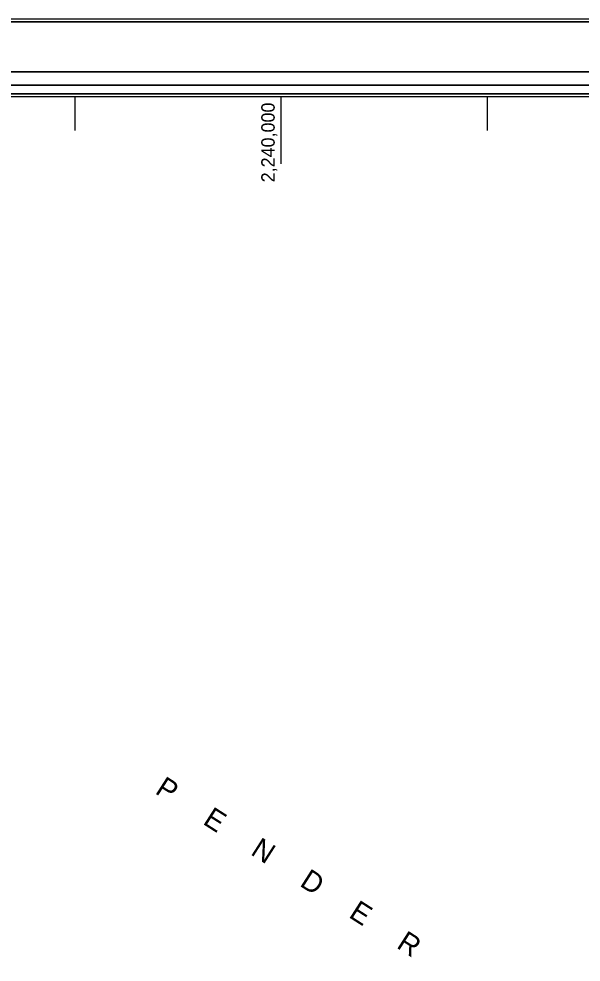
# Model space of a CAD drawing. Extents: x 5197761 to 5514561, y 1890130 to 2080942.
# Drawn here: x 5458064 to 5485322, y 2029172 to 2074930 of the extents above; entities that cross this region are included whole.
import ezdxf

# ---------------------------------------------------------------- set-up
doc = ezdxf.new("R2010")
doc.units = 0
for name, color, linetype in [('Map Preparation Base StatePlane Tick Label', 7, 'Continuous'), ('Map Preparation Base StatePlane Tick Mark', 7, 'Continuous'), ('Map Preparation Border Antique Large Shape', 7, 'Continuous'), ('Map Preparation Border Antique Small Shape', 7, 'Continuous'), ('Map Preparation Border Black Inside Shape', 7, 'Continuous'), ('Map Preparation Border Black Middle Shape', 7, 'Continuous'), ('Map Preparation Border Black Outside Shape', 7, 'Continuous'), ('Map Preparation County Outside Label', 7, 'Continuous')]:
    doc.layers.add(name, color=color, linetype=linetype)

msp = doc.modelspace()

# ---------------------------------------------------------------- linework, layer by layer
at = {"layer": 'Map Preparation Base StatePlane Tick Mark'}
for p, q in [((5460787, 2069519), (5460787, 2071145)), ((5470787, 2067894), (5470787, 2071145)), ((5480787, 2069519), (5480787, 2071145))]:
    msp.add_line(p, q, dxfattribs=at)
at = {"layer": 'Map Preparation Border Antique Large Shape'}
msp.add_lwpolyline([(5197907, 2074783), (5207205, 2074783), (5207205, 1892697), (5512539, 1892697), (5512539, 2072359), (5207205, 2072359), (5207205, 2074783), (5514414, 2074783), (5514414, 1890276), (5197907, 1890276)], close=True, dxfattribs=at)
at = {"layer": 'Map Preparation Border Antique Small Shape'}
msp.add_lwpolyline([(5207791, 2071720), (5208220, 2071720), (5208220, 1893712), (5511524, 1893712), (5511524, 2071291), (5208220, 2071291), (5208220, 2071720), (5207791, 2071720), (5511953, 2071720), (5511953, 1893283), (5208220, 1893283), (5207791, 1893283)], close=True, dxfattribs=at)
at = {"layer": 'Map Preparation Border Black Inside Shape'}
msp.add_lwpolyline([(5208220, 2071291), (5511524, 2071291), (5511524, 1893712), (5208366, 1893712), (5208366, 1893858), (5511378, 1893858), (5511378, 2071145), (5208366, 2071145), (5208366, 1893858), (5208366, 1893712), (5208220, 1893712), (5208220, 1893858)], close=True, dxfattribs=at)
at = {"layer": 'Map Preparation Border Black Middle Shape'}
msp.add_lwpolyline([(5207205, 2072359), (5512539, 2072359), (5512539, 1892697), (5511953, 1892697), (5207791, 1892697), (5207791, 1893283), (5511953, 1893283), (5511953, 2071720), (5207791, 2071720), (5207791, 1892697), (5207205, 1892697)], close=True, dxfattribs=at)
at = {"layer": 'Map Preparation Border Black Outside Shape'}
msp.add_lwpolyline([(5197761, 2074930), (5514561, 2074930), (5514561, 1890130), (5197907, 1890130), (5197907, 1890276), (5514414, 1890276), (5514414, 2074783), (5197907, 2074783), (5197907, 1890130), (5197761, 1890130)], close=True, dxfattribs=at)

# ---------------------------------------------------------------- texts
at = {"layer": 'Map Preparation Base StatePlane Tick Label'}
msp.add_text('2,240,000', height=650, rotation=90, dxfattribs=at).set_placement((5470466, 2067002))
at = {"layer": 'Map Preparation County Outside Label'}
msp.add_text('P     E     N     D     E     R', height=1000, rotation=327.3995, dxfattribs=at).set_placement((5464620, 2037383))

doc.saveas('drawing.dxf')
